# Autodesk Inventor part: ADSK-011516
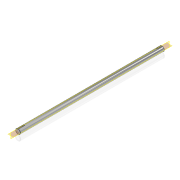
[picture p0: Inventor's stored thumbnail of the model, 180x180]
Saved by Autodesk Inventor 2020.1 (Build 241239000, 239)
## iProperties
Created: 1999-12
Part Number: ADSK-011516
Material: Acier doux
Document SubType Name: Modeling
Designer: sspink
Density: 7.86 g/cm^3
Appearance: Chrom - poliert
Mass: 1349.45 g
Surface Area: 351.274 cm^2
Volume: 171.686 cm^3
Control State: 0
Master: False
Checked Out: False
Shininess: 0.0
Length Units: 11269
Angle Units: 11279
Time Units: 11290
Mass Units: 11283
Length Display Precision: 3
Angle Display Precision: 2
Compacted: True
DocNumber: ADSK-011516.ipt
Folder: 01 - Themengebiete\Simplification\
VDS_Category: 3D Komponenten
Dimensions: 20x20x548 mm
Mass: 1,349 kg
Density: 0.0
Volumn: 0.0
Area: 0.0
PropertySet Name: Model Information
Author: sspink
Revision Number: -
Title: shaft
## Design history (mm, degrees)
chamfer "Fase1" distance "d3" = 1; stored, may be unused: second distance "d4" = 2, angle "d5" = 45 deg
workplane "Arbeitsebene1"
sketch "Skizze2"
  geometry: L1 (-2.5, -274)-(2.5, -274); L2 (2.5, -274)-(2.5, -254); L3 (-2.5, -254)-(-2.5, -274); L4 (9, -274)-(-9, -274) reference; A1 r 2.5 centre (0, -254) between (2.5, -254) and (-2.5, -254); 2 further points
  constraints: 6 end point, 2 midpoint, 2 point on circle, 2 tangent, 1 centre point, 1 horizontal, 1 parallel, 1 perpendicular
  dimensions: "d6" = 5 distance of L1.start L1.end; "d7" = 20 distance of L1.end L2.end
extrude "Extrusion2" cut sketch "Skizze2" distance "d8" = 2; taper "d9" = 0 deg
sketch "Skizze3"
  geometry: L1 (-9, 274)-(9, 274) reference; L2 (-2.5, 274)-(-2.5, 254); L3 (2.5, 254)-(2.5, 274); A1 r 2.5 centre (0, 254) between (-2.5, 254) and (2.5, 254); 2 further points
  constraints: 4 end point, 2 point on circle, 2 point on line, 2 tangent, 2 vertical, 1 centre point, 1 midpoint, 1 perpendicular, 1 vertical alignment
  dimensions: "d10" = 2.5 radius of A1; "d11" = 20 distance of L2.start L2.end
extrude "Extrusion3" cut sketch "Skizze3" distance "d12" = 2; taper "d13" = 0 deg
node "Solide1"
  node "Extrusion1" dims "d1" = 548, "d2" = 0
sketch "Sketch1"
  geometry: C1 r 10 at (0, 0); 1 further point
  constraints: 1 centre point, 1 coincident
  dimensions: "d0" = 20 diameter of C1
node "Corps solides"
node "Corps surfaciques"
